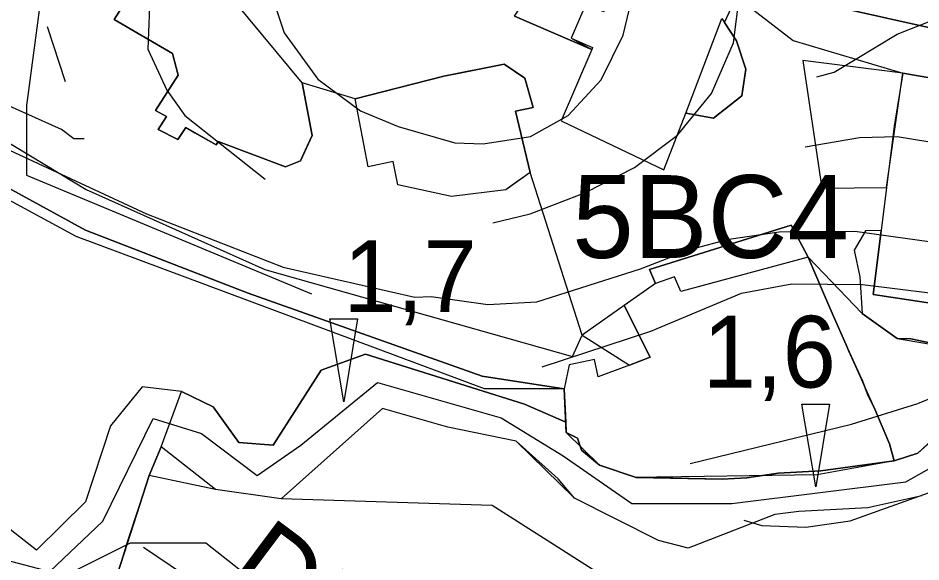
# Model space of a CAD drawing. Extents: x -684583 to -680383, y -1157874 to -1154904.
# Drawn here: x -683367.4 to -683203.8, y -1156997 to -1156898.5 of the extents above; entities that cross this region are included whole.
import ezdxf

# ---------------------------------------------------------------- set-up
doc = ezdxf.new("R2010")
doc.units = 0
for name, color, linetype in [('01_OBVOD PÚ', 7, 'Continuous'), ('01_PRVKY PRŮZKUMU', 7, 'Continuous'), ('01_VRSTEVNICE', 7, 'Continuous'), ('02_KULTURY STAV', 7, 'Continuous'), ('03_PC_OBJEKTY_NÁVRH', 7, 'Continuous'), ('05_VHO_V_TOK', 7, 'Continuous'), ('06_BIOGEOGRAFIE', 7, 'Continuous'), ('06_ÚSES_BK', 7, 'Continuous')]:
    doc.layers.add(name, color=color, linetype=linetype)

msp = doc.modelspace()

# ---------------------------------------------------------------- linework, layer by layer
at = {"layer": '01_OBVOD PÚ'}
for points in [[(-683229.67, -1156980.94), (-683235.38, -1156981.74), (-683239.86, -1156982), (-683248.78, -1156981.85), (-683251.28, -1156981.58), (-683252.2, -1156981.68), (-683255.44, -1156981.69), (-683262.06, -1156979.5), (-683265.34, -1156976.77), (-683266.08, -1156974.59), (-683268.1, -1156973.55), (-683268.47, -1156965.64), (-683283.31, -1156963.36), (-683325.77, -1156948.29), (-683355.2, -1156936.88), (-683380.8, -1156922.96)], [(-683380.8, -1156922.96), (-683355.2, -1156936.88), (-683325.77, -1156948.29), (-683283.31, -1156963.36), (-683268.47, -1156965.64), (-683268.1, -1156973.55), (-683266.08, -1156974.59), (-683265.34, -1156976.77), (-683262.06, -1156979.5), (-683255.44, -1156981.69), (-683252.2, -1156981.68), (-683251.28, -1156981.58), (-683248.78, -1156981.85), (-683239.86, -1156982)], [(-683239.86, -1156982), (-683235.38, -1156981.74), (-683229.67, -1156980.94), (-683221.95, -1156980.5), (-683208.69, -1156978.71), (-683209.52, -1156975.62), (-683212.37, -1156968.92), (-683213.4, -1156966.9), (-683214.54, -1156963.87), (-683217.38, -1156957.68), (-683219.74, -1156952.33), (-683221.48, -1156948.29), (-683224.28, -1156941.81), (-683214.44, -1156951.99), (-683208.1, -1156956.53), (-683205.63, -1156956.61), (-683196.99, -1156958.37)], [(-683196.99, -1156958.37), (-683205.63, -1156956.61), (-683208.1, -1156956.53), (-683214.44, -1156951.99), (-683224.28, -1156941.81), (-683221.48, -1156948.29), (-683219.74, -1156952.33), (-683217.38, -1156957.68), (-683216.87, -1156958.81), (-683215.39, -1156962.13), (-683214.87, -1156963.18), (-683214.54, -1156963.87), (-683213.4, -1156966.9), (-683212.37, -1156968.92), (-683209.52, -1156975.62), (-683208.69, -1156978.71), (-683221.95, -1156980.5), (-683229.67, -1156980.94)]]:
    msp.add_lwpolyline(points, dxfattribs=at)
at = {"layer": '01_PRVKY PRŮZKUMU'}
for points in [[(-683199.16, -1156972.48), (-683204.37, -1156977.31), (-683208.69, -1156978.71), (-683222.6, -1156981.21), (-683255.44, -1156981.69), (-683262.06, -1156979.5), (-683268.1, -1156973.55), (-683268.47, -1156965.64), (-683282.94, -1156965.64), (-683356.94, -1156938.03), (-683380.59, -1156925.22)], [(-683389.86, -1156998.77), (-683362.19, -1157001.09), (-683347.07, -1156993.53), (-683333.41, -1156993.53), (-683286.36, -1157030.61), (-683241.13, -1157071.1), (-683214.31, -1157093.06), (-683204.8, -1157088.06), (-683190.17, -1157081.47)]]:
    msp.add_lwpolyline(points, dxfattribs=at)
at = {"layer": '01_VRSTEVNICE'}
for points in [[(-683355.46, -1156920.38), (-683357.32, -1156920.38), (-683359.6, -1156918.67), (-683379, -1156909.97), (-683394.41, -1156905.12), (-683416.09, -1156903.12), (-683451.6, -1156904.12), (-683467.44, -1156903.26), (-683488.83, -1156898.7), (-683514.51, -1156891.42), (-683524.64, -1156887.14), (-683536.19, -1156880.15), (-683557.73, -1156864.75), (-683582.98, -1156844.92), (-683583.55, -1156843.64), (-683597.53, -1156831.09), (-683608.8, -1156823.38), (-683612.08, -1156820.24), (-683615.22, -1156814.68), (-683619.21, -1156804.55), (-683621.49, -1156791.72), (-683623.36, -1156785.52)], [(-683417.2, -1156874.64), (-683409.69, -1156870.63), (-683380.43, -1156866.6), (-683370.73, -1156863.89), (-683361.31, -1156860.04), (-683353.04, -1156854.91), (-683343.05, -1156844.35), (-683334.49, -1156831.66), (-683329.5, -1156826.95), (-683322.66, -1156824.67), (-683321.23, -1156825.24), (-683321.23, -1156827.8), (-683323.8, -1156833.94), (-683324.79, -1156843.07), (-683326.65, -1156852.2), (-683334.21, -1156875.02), (-683341.63, -1156888.71), (-683343.48, -1156893.28), (-683343.91, -1156904.12), (-683340.48, -1156911.54), (-683337.2, -1156916.1), (-683322.65, -1156927.66)], [(-683281.4, -1156935.58), (-683274.61, -1156933.93), (-683264.6, -1156930.08), (-683255.75, -1156925.52), (-683247.91, -1156919.67), (-683241.78, -1156912.11), (-683237.78, -1156902.98), (-683236.64, -1156893.85), (-683236.64, -1156886.29)], [(-683322.94, -1156889.85), (-683319.23, -1156901.12), (-683313.1, -1156909.54), (-683305.4, -1156915.25), (-683298.55, -1156918.1), (-683288.28, -1156921.09), (-683283.14, -1156921.24), (-683274.58, -1156919.95), (-683267.74, -1156916.1), (-683261.74, -1156909.68), (-683257.75, -1156901.55), (-683256.33, -1156895.56)], [(-683222.66, -1156909.11), (-683219.52, -1156908.26), (-683208.11, -1156901.41), (-683199.55, -1156897.99), (-683190.99, -1156897.13), (-683182.44, -1156898.13), (-683176.73, -1156899.98), (-683169.6, -1156903.83), (-683164.75, -1156908.54)], [(-683362.17, -1156899.98), (-683358.89, -1156909.97)], [(-683372.44, -1156920.81), (-683344.19, -1156933.93), (-683319.37, -1156943.63), (-683295.55, -1156949.05), (-683292.56, -1156948.91), (-683282.29, -1156950.34), (-683273.44, -1156949.91), (-683254.61, -1156943.92), (-683245.48, -1156940.35), (-683238.64, -1156938.5), (-683229.51, -1156937.21), (-683215.81, -1156937.07), (-683197.56, -1156939.64)], [(-683224.8, -1156921.81), (-683214.96, -1156920.1), (-683208.11, -1156919.95), (-683180.72, -1156924.38), (-683155.19, -1156921.52)], [(-683272.46, -1156961.66), (-683252.76, -1156955.19), (-683236.35, -1156948.34), (-683227.23, -1156946.63), (-683214.39, -1156946.77), (-683195.84, -1156949.05), (-683184.72, -1156949.62), (-683158.19, -1156949.05), (-683150.2, -1156950.76), (-683142.21, -1156953.47), (-683136.93, -1156954.04)], [(-683245.63, -1156979.15), (-683216.38, -1156972.02), (-683204.4, -1156968.31), (-683192.42, -1156963.32), (-683184.43, -1156961.89), (-683174.45, -1156964.03), (-683167.46, -1156969.74), (-683163.61, -1156975.44), (-683160.18, -1156989.14), (-683157.62, -1156995.98), (-683152.91, -1157002.97), (-683146.78, -1157007.68), (-683130.23, -1157016.81), (-683126.23, -1157018.23), (-683121.24, -1157018.8), (-683115.25, -1157016.81)], [(-683235.93, -1156989.42), (-683232.65, -1156990.42), (-683224.66, -1156990.7), (-683216.67, -1156989.56), (-683196.7, -1156982.43), (-683190.71, -1156981.57), (-683184.72, -1156983), (-683181.15, -1156986.57), (-683175.02, -1157005.11), (-683169.03, -1157014.1), (-683165.46, -1157017.66), (-683161.32, -1157020.66), (-683142.07, -1157030.5), (-683134.22, -1157035.21), (-683129.94, -1157040.2), (-683127.52, -1157044.2)]]:
    msp.add_lwpolyline(points, dxfattribs=at)
at = {"layer": '02_KULTURY STAV'}
for points in [[(-683144.49, -1156888.23), (-683152.95, -1156888.13), (-683152.58, -1156881.97), (-683158.53, -1156882.38), (-683159.41, -1156869.43), (-683169.55, -1156869.99), (-683191.74, -1156873.92), (-683222.81, -1156869.5), (-683224.01, -1156876.75), (-683224.35, -1156878.87), (-683225.64, -1156887.39), (-683226.54, -1156894.73), (-683195.64, -1156901.71), (-683187.21, -1156902.59), (-683178.49, -1156903.51), (-683152.9, -1156906.21), (-683144.46, -1156907.09), (-683144.45, -1156905.71)], [(-683248.91, -1156884.8), (-683254.22, -1156882.08), (-683254.73, -1156881.82), (-683261.26, -1156897.34), (-683264.57, -1156895.93), (-683267.18, -1156902.14), (-683263.48, -1156904.15), (-683263.48, -1156904.15), (-683277.49, -1156898.15), (-683269.72, -1156886.67), (-683259.2, -1156871.13), (-683254.18, -1156873.02), (-683247.05, -1156880.41)], [(-683248.91, -1156884.8), (-683254.22, -1156882.08), (-683254.22, -1156882.08), (-683254.73, -1156881.82), (-683261.26, -1156897.34), (-683264.57, -1156895.93), (-683267.18, -1156902.14), (-683263.33, -1156903.79), (-683263.48, -1156904.15), (-683268.99, -1156917.08), (-683250.38, -1156925.97), (-683246.44, -1156915.69), (-683239.87, -1156898.53), (-683239.4, -1156899.27), (-683237.24, -1156894.54), (-683238.11, -1156893.93), (-683242.01, -1156891.2), (-683249.43, -1156886.03)], [(-683341.13, -1156884.74), (-683350, -1156898.74), (-683339.45, -1156904.89), (-683338.41, -1156908.84), (-683342.51, -1156915.19), (-683340.54, -1156916.32), (-683342.07, -1156918.67), (-683338.48, -1156920.49), (-683337.06, -1156918.3), (-683335.43, -1156919.24), (-683331.56, -1156921.44), (-683331.19, -1156920.81), (-683318.96, -1156925.43), (-683316.28, -1156924.32), (-683315.03, -1156921.67), (-683314.15, -1156919.77), (-683315.94, -1156910.21), (-683332.75, -1156889.93)], [(-683239.87, -1156898.53), (-683239.4, -1156899.27), (-683237.27, -1156902.58), (-683235.55, -1156907.76), (-683236.29, -1156912.57), (-683241.42, -1156916.59), (-683246.44, -1156915.69)], [(-683207.07, -1156908.47), (-683225.2, -1156906.13), (-683221.8, -1156929.26), (-683210.05, -1156929.14)], [(-683413.22, -1156907.01), (-683380.86, -1156914.04), (-683355.11, -1156929.55), (-683322.74, -1156944.05), (-683266.98, -1156959.79), (-683265.23, -1156955.91), (-683256.63, -1156961.33), (-683260.88, -1156962.95), (-683262.33, -1156963.5), (-683262.98, -1156960.35), (-683267.55, -1156961.29), (-683268.47, -1156965.64), (-683283.31, -1156963.36), (-683325.77, -1156948.29), (-683355.2, -1156936.88), (-683380.8, -1156922.96), (-683394.92, -1156921.16), (-683404.54, -1156921.9), (-683418.18, -1156922.4)], [(-683306.38, -1156913.1), (-683301.17, -1156911.77), (-683290.26, -1156908.98), (-683286.27, -1156908.19), (-683279.36, -1156906.84), (-683275.62, -1156909.34), (-683274.11, -1156914.66), (-683277.31, -1156915.35), (-683274.65, -1156926.43), (-683277.9, -1156928.77), (-683279.04, -1156929.59), (-683288.9, -1156930.79), (-683298.6, -1156928.69), (-683299.48, -1156924.45), (-683303.98, -1156925.44)], [(-683207.07, -1156908.47), (-683208.67, -1156918.05), (-683210.05, -1156929.14), (-683211.03, -1156936.94), (-683211.15, -1156937.97), (-683212.47, -1156948.55), (-683187.64, -1156952.28), (-683187.03, -1156946.98), (-683183.98, -1156947.39), (-683185.13, -1156957.82), (-683168.02, -1156956.73), (-683146.66, -1156951.91), (-683173.83, -1156920.44), (-683177.73, -1156917.85), (-683184.05, -1156913.74), (-683194.42, -1156910.61), (-683196.29, -1156910.35)], [(-683251.92, -1156946.55), (-683253.01, -1156944.05), (-683227.33, -1156935.99), (-683224.28, -1156941.81), (-683247.32, -1156948), (-683248.48, -1156945.36)], [(-683211.15, -1156937.97), (-683211.03, -1156936.94), (-683213.85, -1156937.02), (-683215.91, -1156940.55), (-683214.89, -1156945.35), (-683214.44, -1156951.99), (-683208.1, -1156956.53), (-683196.99, -1156958.37), (-683185.13, -1156957.82), (-683183.98, -1156947.39), (-683187.03, -1156946.98), (-683187.64, -1156952.28), (-683212.47, -1156948.55)], [(-683268.47, -1156965.64), (-683268.1, -1156973.55), (-683266.08, -1156974.59), (-683265.34, -1156976.77), (-683262.06, -1156979.5), (-683255.44, -1156981.69), (-683251.28, -1156981.58), (-683248.78, -1156981.85), (-683239.86, -1156982), (-683235.38, -1156981.74), (-683229.67, -1156980.94), (-683221.95, -1156980.5), (-683208.69, -1156978.71), (-683209.52, -1156975.62), (-683212.37, -1156968.92), (-683213.4, -1156966.9), (-683214.54, -1156963.87), (-683215.39, -1156962.13), (-683216.87, -1156958.81), (-683217.38, -1156957.68), (-683219.74, -1156952.33), (-683221.48, -1156948.29), (-683224.28, -1156941.81), (-683247.32, -1156948), (-683248.48, -1156945.36), (-683251.92, -1156946.55), (-683257.61, -1156950.56), (-683252.87, -1156959.89), (-683256.63, -1156961.33), (-683260.88, -1156962.95), (-683262.33, -1156963.5), (-683262.98, -1156960.35), (-683267.55, -1156961.29)], [(-683257.61, -1156950.56), (-683265.23, -1156955.91), (-683256.63, -1156961.33), (-683252.87, -1156959.89)]]:
    msp.add_lwpolyline(points, close=True, dxfattribs=at)
for points in [[(-683380.86, -1156914.04), (-683355.11, -1156929.55), (-683322.74, -1156944.05), (-683266.98, -1156959.79), (-683265.23, -1156955.91), (-683274.65, -1156926.43), (-683279.04, -1156929.59), (-683288.9, -1156930.79), (-683298.6, -1156928.69), (-683299.48, -1156924.45), (-683303.98, -1156925.44), (-683306.38, -1156913.1), (-683315.94, -1156910.21), (-683314.15, -1156919.77), (-683316.28, -1156924.32), (-683318.96, -1156925.43), (-683331.19, -1156920.81), (-683331.56, -1156921.44), (-683337.06, -1156918.3), (-683338.48, -1156920.49), (-683342.07, -1156918.67), (-683340.54, -1156916.32), (-683342.51, -1156915.19), (-683338.41, -1156908.84), (-683339.45, -1156904.89), (-683350, -1156898.74), (-683341.13, -1156884.74)], [(-683277.49, -1156898.15), (-683263.48, -1156904.15), (-683268.99, -1156917.08), (-683250.38, -1156925.97), (-683246.44, -1156915.69), (-683241.42, -1156916.59), (-683236.29, -1156912.57), (-683235.55, -1156907.76), (-683237.27, -1156902.58), (-683239.4, -1156899.27), (-683237.24, -1156894.54), (-683226.96, -1156902.55), (-683207.07, -1156908.47), (-683225.2, -1156906.13), (-683221.8, -1156929.26), (-683210.05, -1156929.14), (-683211.03, -1156936.94), (-683213.85, -1156937.02), (-683215.91, -1156940.55), (-683214.89, -1156945.35), (-683214.44, -1156951.99), (-683224.28, -1156941.81), (-683227.33, -1156935.99), (-683253.01, -1156944.05), (-683251.92, -1156946.55), (-683257.61, -1156950.56), (-683265.23, -1156955.91), (-683274.65, -1156926.43), (-683277.31, -1156915.35), (-683274.11, -1156914.66), (-683275.62, -1156909.34), (-683279.36, -1156906.84), (-683290.26, -1156908.98), (-683301.17, -1156911.77), (-683306.38, -1156913.1), (-683315.94, -1156910.21), (-683332.75, -1156889.93)], [(-683237.24, -1156894.54), (-683226.96, -1156902.55), (-683207.07, -1156908.47), (-683196.29, -1156910.35), (-683194.42, -1156910.61), (-683184.05, -1156913.74), (-683177.73, -1156917.85), (-683170.2, -1156909.42), (-683169.67, -1156904.44), (-683178.49, -1156903.51), (-683187.21, -1156902.59), (-683195.64, -1156901.71), (-683226.54, -1156894.73)], [(-683380.8, -1156922.96), (-683355.2, -1156936.88), (-683325.77, -1156948.29), (-683283.31, -1156963.36), (-683268.47, -1156965.64), (-683268.19, -1156971.66), (-683275.66, -1156968.44), (-683304.5, -1156959.39), (-683312.51, -1156962.26), (-683321.23, -1156975.87), (-683327.45, -1156975.35), (-683332.11, -1156968.93), (-683337.83, -1156966.11), (-683344.97, -1156965.28), (-683350.67, -1156972.37), (-683355.24, -1156986.1), (-683364.12, -1156994.87), (-683372.87, -1156988.03)], [(-683199.16, -1156972.48), (-683204.37, -1156977.31), (-683208.69, -1156978.71), (-683209.52, -1156975.62), (-683212.37, -1156968.92), (-683217.38, -1156957.68), (-683219.74, -1156952.33), (-683221.48, -1156948.29), (-683224.28, -1156941.81), (-683214.44, -1156951.99), (-683208.1, -1156956.53), (-683196.99, -1156958.37)], [(-683203.65, -1156985.03), (-683213.41, -1156987.19), (-683225.95, -1156987.87), (-683230.28, -1156988.44), (-683246.03, -1156994.49), (-683251.36, -1156993.14), (-683266.62, -1156985.44), (-683269.55, -1156981.97), (-683277.18, -1156975.14), (-683289.55, -1156972.59), (-683301.39, -1156969.2), (-683319.75, -1156985.6), (-683331.68, -1156983.88), (-683341.48, -1156976.18), (-683337.83, -1156966.11), (-683332.11, -1156968.93), (-683327.45, -1156975.35), (-683321.23, -1156975.87), (-683312.51, -1156962.26), (-683304.5, -1156959.39), (-683275.66, -1156968.44), (-683268.19, -1156971.66), (-683268.1, -1156973.55), (-683266.08, -1156974.59), (-683265.34, -1156976.77), (-683262.06, -1156979.5), (-683255.44, -1156981.69), (-683252.2, -1156981.68), (-683251.28, -1156981.58), (-683248.78, -1156981.85), (-683239.86, -1156982), (-683235.38, -1156981.74), (-683229.67, -1156980.94), (-683221.95, -1156980.5), (-683208.69, -1156978.71), (-683204.37, -1156977.31), (-683199.16, -1156972.48)], [(-683370.86, -1157001.24), (-683367.03, -1157002.46), (-683359.7, -1157003.17), (-683352.15, -1157001.15), (-683349.45, -1156999.14), (-683343.69, -1156981.37), (-683341.48, -1156976.18), (-683337.83, -1156966.11), (-683344.97, -1156965.28), (-683350.67, -1156972.37), (-683355.24, -1156986.1), (-683364.12, -1156994.87), (-683372.87, -1156988.03)], [(-683203.65, -1156985.03), (-683213.41, -1156987.19), (-683225.95, -1156987.87), (-683230.28, -1156988.44), (-683246.03, -1156994.49), (-683251.36, -1156993.14), (-683266.62, -1156985.44), (-683277.18, -1156975.14), (-683289.55, -1156972.59), (-683301.39, -1156969.2), (-683319.75, -1156985.6), (-683331.68, -1156983.88), (-683341.48, -1156976.18), (-683343.69, -1156981.37), (-683349.45, -1156999.14), (-683327.49, -1157011.01), (-683308.96, -1157026.01), (-683248.52, -1157087.99), (-683232.88, -1157099.6), (-683221.99, -1157102.98), (-683204.36, -1157091.01), (-683192.73, -1157085.68)]]:
    msp.add_lwpolyline(points, dxfattribs=at)
at = {"layer": '03_PC_OBJEKTY_NÁVRH'}
for points in [[(-683361.62, -1156882), (-683365.92, -1156914.32), (-683365.92, -1156926.95), (-683314.29, -1156948.44)], [(-683226.99, -1157090.37), (-683323.32, -1157008.82), (-683344.73, -1156994.4)]]:
    msp.add_lwpolyline(points, dxfattribs=at)
at = {"layer": '05_VHO_V_TOK'}
for points in [[(-683310.92, -1156952.99), (-683305.92, -1156952.99), (-683308.42, -1156967.99)], [(-683225.39, -1156968.41), (-683220.39, -1156968.41), (-683222.89, -1156983.41)]]:
    msp.add_lwpolyline(points, close=True, dxfattribs=at)
msp.add_lwpolyline([(-683378.73, -1156994.28), (-683361.67, -1156998.74), (-683352.07, -1156989.61), (-683342.95, -1156971), (-683334.18, -1156973.73), (-683324.11, -1156981.32), (-683316.17, -1156975.87), (-683302.3, -1156964.48), (-683279.9, -1156970.88), (-683268.64, -1156977.76), (-683256.2, -1156986.41), (-683238.07, -1156986.41), (-683206.55, -1156982.5), (-683191.86, -1156974.2), (-683180.36, -1156978.71), (-683174.44, -1156992.7), (-683172.9, -1157010.12), (-683165.9, -1157018.9), (-683149.43, -1157022.45), (-683104.87, -1157050.79), (-683100.25, -1157059.8), (-683098, -1157072.96), (-683095.63, -1157123.11), (-683121.58, -1157197.8)], dxfattribs=at)
at = {"layer": '06_BIOGEOGRAFIE'}
for points in [[(-683099.47, -1156889.99), (-683108.08, -1156852.09), (-683133.91, -1156841.76), (-683133.91, -1156814.2), (-683132.19, -1156784.91), (-683147.69, -1156747.02), (-683189.01, -1156748.74), (-683242.39, -1156712.57), (-683235.51, -1156631.61), (-683171.79, -1156531.71), (-683097.75, -1156511.04), (-683004.76, -1156526.54), (-682887.67, -1156483.48), (-682868.73, -1156459.36), (-682823.96, -1156452.47), (-682839.46, -1156516.2), (-682863.56, -1156605.77), (-682887.67, -1156736.68), (-682923.83, -1156891.71), (-682934.16, -1156915.82), (-682965.16, -1156929.6), (-683004.76, -1156926.16)], [(-683605.53, -1156693.94), (-683552.15, -1156773.17), (-683505.66, -1156862.74), (-683385.12, -1156876.52), (-683240.48, -1156867.91), (-682983.91, -1156935.09), (-682923.69, -1156998.38), (-682921.97, -1157094.84), (-682923.69, -1157198.19), (-682892.7, -1157272.26), (-682746.33, -1157329.1), (-682572.41, -1157337.72), (-682417.44, -1157289.49), (-682386.73, -1157266.62)], [(-683662.04, -1156787.77), (-683658.6, -1156877.34), (-683631.05, -1156927.29), (-683541.5, -1156975.52), (-683489.85, -1157028.92), (-683414.08, -1157027.2), (-683362.42, -1157025.48), (-683360.7, -1157063.37), (-683464.02, -1157132.27), (-683493.29, -1157163.28), (-683474.35, -1157189.11), (-683407.19, -1157171.89), (-683317.65, -1157115.05), (-683269.44, -1157104.71), (-683207.44, -1157173.61), (-683186.78, -1157259.74), (-683105.85, -1157416.48), (-683069.69, -1157530.17), (-683073.13, -1157580.12), (-683097.24, -1157628.35), (-683264.27, -1157657.63), (-683431.3, -1157647.3), (-683531.17, -1157605.96), (-683636.21, -1157542.23), (-683651.71, -1157521.56), (-683682.7, -1157519.83), (-683708.53, -1157528.45), (-683818.74, -1157547.39), (-683870.4, -1157518.11), (-683980.6, -1157521.56), (-684052.92, -1157490.55), (-684171.74, -1157400.98), (-684213.07, -1157375.14), (-684250.95, -1157388.92), (-684249.23, -1157437.15), (-684237.17, -1157466.44), (-684170.02, -1157518.11), (-684097.7, -1157562.9), (-684011.6, -1157605.96), (-683953.05, -1157602.51), (-683891.06, -1157626.63), (-683835.96, -1157619.74), (-683789.47, -1157599.07), (-683713.7, -1157578.4), (-683625.88, -1157592.18), (-683551.84, -1157667.97), (-683445.07, -1157736.87), (-683346.92, -1157771.32), (-683179.89, -1157767.87), (-683081.74, -1157773.04), (-683016.71, -1157810.65), (-682999.16, -1157844)]]:
    msp.add_spline(points, degree=3, dxfattribs=at)
at = {"layer": '06_ÚSES_BK'}
for points in [[(-683380.8, -1156922.96), (-683355.2, -1156936.88), (-683325.77, -1156948.29), (-683283.31, -1156963.36), (-683268.47, -1156965.64), (-683268.19, -1156971.66), (-683268.1, -1156973.55), (-683266.08, -1156974.59), (-683265.34, -1156976.77), (-683262.06, -1156979.5), (-683255.44, -1156981.69), (-683239.86, -1156982), (-683235.38, -1156981.74), (-683229.67, -1156980.94), (-683221.95, -1156980.5), (-683208.69, -1156978.71), (-683204.37, -1156977.31), (-683198.55, -1156972.1)], [(-683158.62, -1157178.84), (-683156.25, -1157161.12), (-683151.27, -1157139.55), (-683145.65, -1157125.76), (-683142.92, -1157117.14), (-683133.51, -1157096.13), (-683130.44, -1157090.32), (-683127.87, -1157085.44), (-683146.23, -1157074.82), (-683146.88, -1157076.28), (-683149.7, -1157070.65), (-683281.53, -1156986.77), (-683319.75, -1156985.6), (-683331.68, -1156983.88), (-683343.69, -1156981.37), (-683347.61, -1156993.23), (-683349.45, -1156999.14), (-683352.15, -1157001.15), (-683359.7, -1157003.17), (-683367.03, -1157002.46), (-683370.86, -1157001.24)]]:
    msp.add_lwpolyline(points, dxfattribs=at)

# ---------------------------------------------------------------- texts
at = {"layer": '03_PC_OBJEKTY_NÁVRH'}
msp.add_text('DR12', height=15, rotation=323.1279, dxfattribs=at).set_placement((-683330.6, -1157000.5))
at = {"layer": '05_VHO_V_TOK'}
for s, p in [('1,7', (-683308.49, -1156951.72)), ('1,6', (-683243.38, -1156965.41))]:
    msp.add_text(s, height=13, dxfattribs=at).set_placement(p)
at = {"layer": '06_BIOGEOGRAFIE'}
msp.add_text('5BC4', height=15, dxfattribs=at).set_placement((-683267.02, -1156941.93))

doc.saveas('drawing.dxf')
